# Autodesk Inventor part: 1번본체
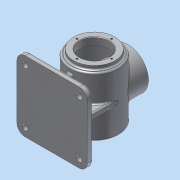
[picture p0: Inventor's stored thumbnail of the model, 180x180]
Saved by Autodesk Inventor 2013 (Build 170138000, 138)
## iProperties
Created: 2015-07
Part Number: 1번본체
Material: 알루미늄 6061
Document SubType Name: Modeling
Designer: dgall
Density: 2.71 g/cm^3
Mass: 1277.74 g
Surface Area: 1267.61 cm^2
Volume: 471.49 cm^3
Author: dgall
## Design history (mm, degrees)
sketch "스케치1"
  geometry: L1 (0, 58.5)-(0, -58.5); L2 (38, 58.5)-(38, 51.5); L3 (38, 51.5)-(45, 51.5); L4 (45, 51.5)-(45, -58.5); L5 (45, -58.5)-(0, -58.5); L6 (38, 58.5)-(27, 58.5); L7 (27, 58.5)-(27, 44.5); L8 (27, 44.5)-(40, 44.5); L9 (40, 44.5)-(40, -51.5); L10 (40, -51.5)-(0, -51.5); 2 further points
  constraints: 20 end point, 6 parallel, 3 perpendicular, 2 coincident, 1 horizontal alignment, 1 midpoint, 1 point on line, 1 vertical
  dimensions: "d0" = 117 distance of L1.start L1.end; "d2" = 90 diameter of L4 L1; "d3" = 80 diameter of L9 L1; "d4" = 7 distance between parallel lines of L5 L10; "d5" = 54 diameter of L7 L1; "d6" = 76 diameter of L2 L1; "d7" = 14 distance of L6.end L7.end; "d8" = 7 distance of L2.start L2.end
revolve "회전1" sketch "스케치1" stored, may be unused: angle "d9" = 90 deg
node "작업 평면1"
sketch "스케치2"
  geometry: L1 (65, -68.5)-(-65, -68.5); L2 (-65, -68.5)-(-65, 61.5); L3 (-65, 61.5)-(65, 61.5); L4 (65, 61.5)-(65, -68.5); L5 (-45, -58.5)-(45, -58.5) reference; 3 further points
  constraints: 8 end point, 2 midpoint, 2 parallel, 1 horizontal, 1 perpendicular, 1 vertical alignment
  dimensions: "d11" = 130 distance of L1.start L1.end; "d13" = 130 distance of L1.end L2.end (= d11); "d14" = 10 distance between parallel lines of L5 L1
extrude "돌출1" join sketch "스케치2" distance "d15" = 10; taper "d16" = 0 deg
sketch "스케치3"
  geometry: L1 (-5, 48.5)-(5, 48.5); L2 (5, -41.5)-(-5, -41.5); L3 (45, 8.5)-(45, -1.5); L4 (-45, -1.5)-(-45, 8.5); L5 (-45, 8.5)-(-5, 8.5); L6 (5, 8.5)-(45, 8.5); L7 (-5, -41.5)-(-5, -1.5); L8 (-5, 8.5)-(-5, 48.5); L9 (45, -1.5)-(5, -1.5); L10 (-5, -1.5)-(-45, -1.5); L11 (5, 48.5)-(5, 8.5); L12 (5, -1.5)-(5, -41.5); L13 (-65, 68.5)-(-65, -61.5) reference; 4 further points
  constraints: 24 end point, 10 parallel, 10 perpendicular, 3 horizontal, 3 horizontal alignment, 3 midpoint, 3 vertical alignment
  dimensions: "d17" = 10 distance of L4.start L4.end; "d19" = 10 distance of L1.start L1.end (= d17); "d20" = 90 distance between parallel lines of L2 L1
extrude "돌출2" join sketch "스케치3" stored distance "d21" = 10; taper "d22" = 0 deg
fillet "모깎기1" dims "d23" = 15
sketch "스케치4"
  geometry: C1 r 38 at (0, 0) reference; 1 further point
  constraints: 1 vertical alignment
  dimensions: "d24" = 32 distance of C1.centre point (0, 32)
hole "구멍1" sketch "스케치4" at (0, 32) diameter "d25" = 3.242; stored, may be unused: countersink angle "d29" = 90 deg, drill point angle "d31" = 118 deg; dims "d26" = 8, "d27" = 4, "d28" = 2, "d30" = 10
node "작업 평면2"
sketch "스케치5"
  geometry: L1 (-45, -58.5)-(45, -58.5) reference; C1 r 38 at (0, -3.5); 2 further points
  constraints: 2 vertical alignment, 1 centre point
  dimensions: "d36" = 55 distance from line of C1.centre L1; "d37" = 76 diameter of C1; "d49" = 32 distance of C1.centre point (0, -35.5)
extrude "돌출3" join sketch "스케치5" stored distance "d38" = 10; taper "d39" = 0 deg
hole "구멍2" diameter "d42" = 54; stored, may be unused: countersink angle "d46" = 90 deg, drill point angle "d48" = 0 deg; dims "d40" = 10, "d41" = 10, "d43" = 8, "d44" = 4, "d45" = 2, "d47" = 10
hole "구멍3" sketch "스케치5" diameter "d50" = 3.242; stored, may be unused: countersink angle "d54" = 90 deg, drill point angle "d56" = 118 deg; dims "d51" = 8, "d52" = 4, "d53" = 2, "d55" = 10
sketch "스케치6"
  geometry: C1 r 7.5 at (-50, 53.5); A1 r 15 centre (-50, 53.5) between (-50, 68.5) and (-65, 53.5) reference; 1 further point
  constraints: 1 centre point, 1 coincident
  dimensions: "d60" = 15 diameter of C1
extrude "돌출4" join sketch "스케치6" distance "d62" = 3; taper "d63" = 0 deg
fillet "모깎기2" dims "d64" = 3
hole "구멍4" diameter "d67" = 10; stored, may be unused: countersink angle "d71" = 90 deg, drill point angle "d73" = 0 deg; dims "d65" = 10, "d66" = 10, "d68" = 8, "d69" = 4, "d70" = 2, "d72" = 10
fillet "모깎기3" dims "d80" = 3
fillet "모깎기4" dims "d81" = 3
chamfer "모따기1" distance "d82" = 1; stored, may be unused: second distance "d83" = 2, angle "d84" = 45 deg
sketch "스케치7"
  geometry: C1 r 42 at (0, 0) reference; 1 further point
  constraints: 1 coincident, 1 other
feature "엠보싱1" sketch "스케치7" dims "d0" = 117, "d2" = 90, "d3" = 80, "d4" = 7, "d5" = 54, "d6" = 76, "d7" = 14, "d8" = 7, "d15" = 10, "d85" = 0.5, "d86" = 0
node "솔리드1"
pattern_circular "원형 패턴1" dims angle "d33" = 360 deg
pattern_circular "원형 패턴2" dims angle "d58" = 360 deg
pattern_linear "직사각형 패턴1"
other parameters: "d10" = -78
